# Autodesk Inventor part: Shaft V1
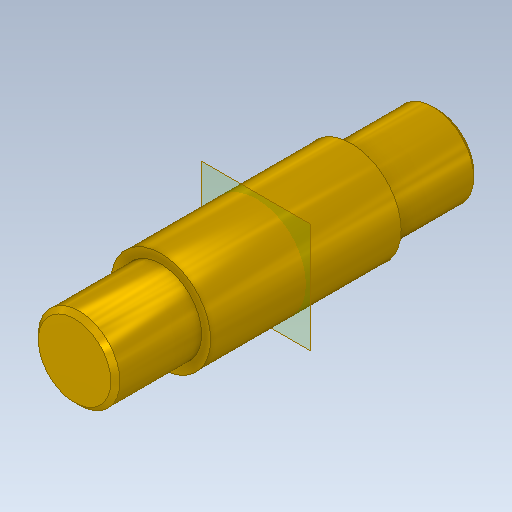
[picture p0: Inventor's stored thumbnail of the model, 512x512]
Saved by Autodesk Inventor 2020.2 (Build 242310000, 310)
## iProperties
Created: 2018-06
Part Number: Shaft V1
Material: Iron, Cast
Document SubType Name: Modeling
Designer: Power User
Density: 7.15 g/cm^3
Appearance: Aluminum - Polished(3)
Mass: 182.904 g
Surface Area: 57.4309 cm^2
Volume: 25.5809 cm^3
Author: Power User
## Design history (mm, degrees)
sketch "Sketch1"
  geometry: C1 r 9 at (0, 0); C2 r 11 at (0, 0); 1 further point
  constraints: 2 centre point, 2 coincident
  dimensions: "d0" = 18 diameter of C1; "d1" = 22 diameter of C2
extrude "Extrusion1" new body sketch "Sketch1" stored distance "d2" = 80; taper "d3" = 0 deg
extrude "Extrusion2" join sketch "Sketch1" stored distance "d4" = 42; taper "d5" = 0 deg
chamfer "Chamfer1" distance "d6" = 1; stored, may be unused: second distance "d7" = 2, angle "d8" = 45 deg
chamfer "Chamfer2" distance "d9" = 1; stored, may be unused: second distance "d10" = 2, angle "d11" = 45 deg
workplane "Work Plane1"
sketch "Sketch2"
  geometry: C1 r 8 at (0, 0) reference; 2 further points
  constraints: 1 coincident
hole "Hole1" sketch "Sketch2" at (0, 0) diameter "d12" = 6; stored, may be unused: countersink angle "d16" = 90 deg, drill point angle "d18" = 118 deg; dims "d13" = 6, "d14" = 8, "d15" = 5, "d17" = 25
body "Solid1"
